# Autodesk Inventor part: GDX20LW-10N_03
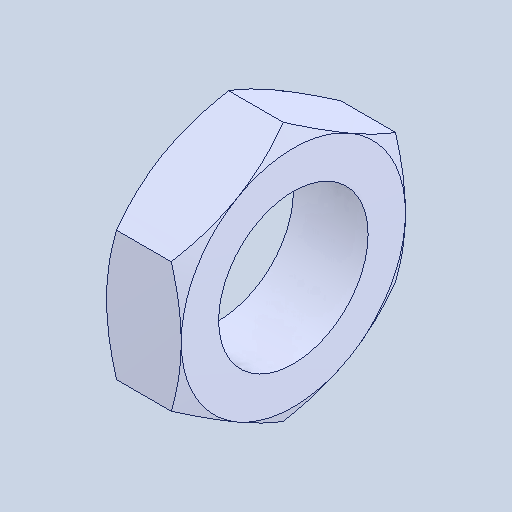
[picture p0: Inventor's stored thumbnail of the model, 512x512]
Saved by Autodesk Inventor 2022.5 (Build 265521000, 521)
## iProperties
Created: 2024-06
Part Number: GDX20LW-10N_03
Material: 一般
Document SubType Name: Modeling
Designer: ImaoCorp
Density: 1 g/cm^3
Appearance: 既定
Author: ImaoCorp
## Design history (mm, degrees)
feature "GDX20LW-10N_03"
node "ソリッド1"
